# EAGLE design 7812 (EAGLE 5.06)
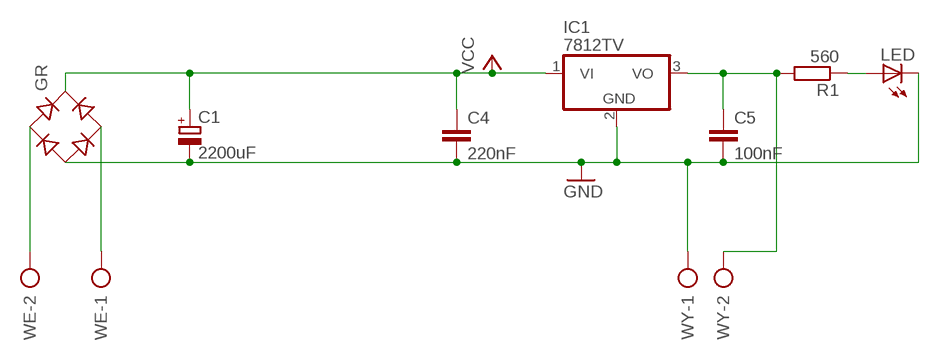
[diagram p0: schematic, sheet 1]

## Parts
C1  2200uF  CPOL-EUE7.5-16  [E7,5-16]
C4  220nF  C-EU025-030X050  [C025-030X050]
C5  100nF  C-EU025-030X050  [C025-030X050]
GR  RB1A  [RB1A]
IC1  7812TV  [TO220V]
LED  LED3MM  [LED3MM]
R1  560  R-EU_0207/10  [0207/10]
WE  AK300/2  [AK300/2]
WY  AK300/2  [AK300/2]

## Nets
GND: C1.- C4.2 C5.2 GR.- IC1.2(GND) LED.K(C) WY.1
N$1: GR.AC1 WE.2
N$2: GR.AC2 WE.1
N$4: C5.1 IC1.3(VO) R1.2 WY.2
N$5: LED.A R1.1
VCC: C1.+ C4.1 GR.+ IC1.1(VI)

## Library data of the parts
C1 = resistor:CPOL-EU: POLARIZED CAPACITOR, European symbol
C4 C5 = rcl:C-EU: CAPACITOR, European symbol
GR = rectifier:RB1A: RECTIFIER 1 A
IC1 = linear:78*: Positive VOLTAGE REGULATOR Source: http://cache.national.com/ds/LM/LM78L05.pdf http://www.fairchildsemi.com/ds/LM/LM7805.pdf
LED = led:LED: LED
R1 = rcl:R-EU_: RESISTOR, European symbol
WE WY = con-ptr500:AK300/2: CONNECTOR

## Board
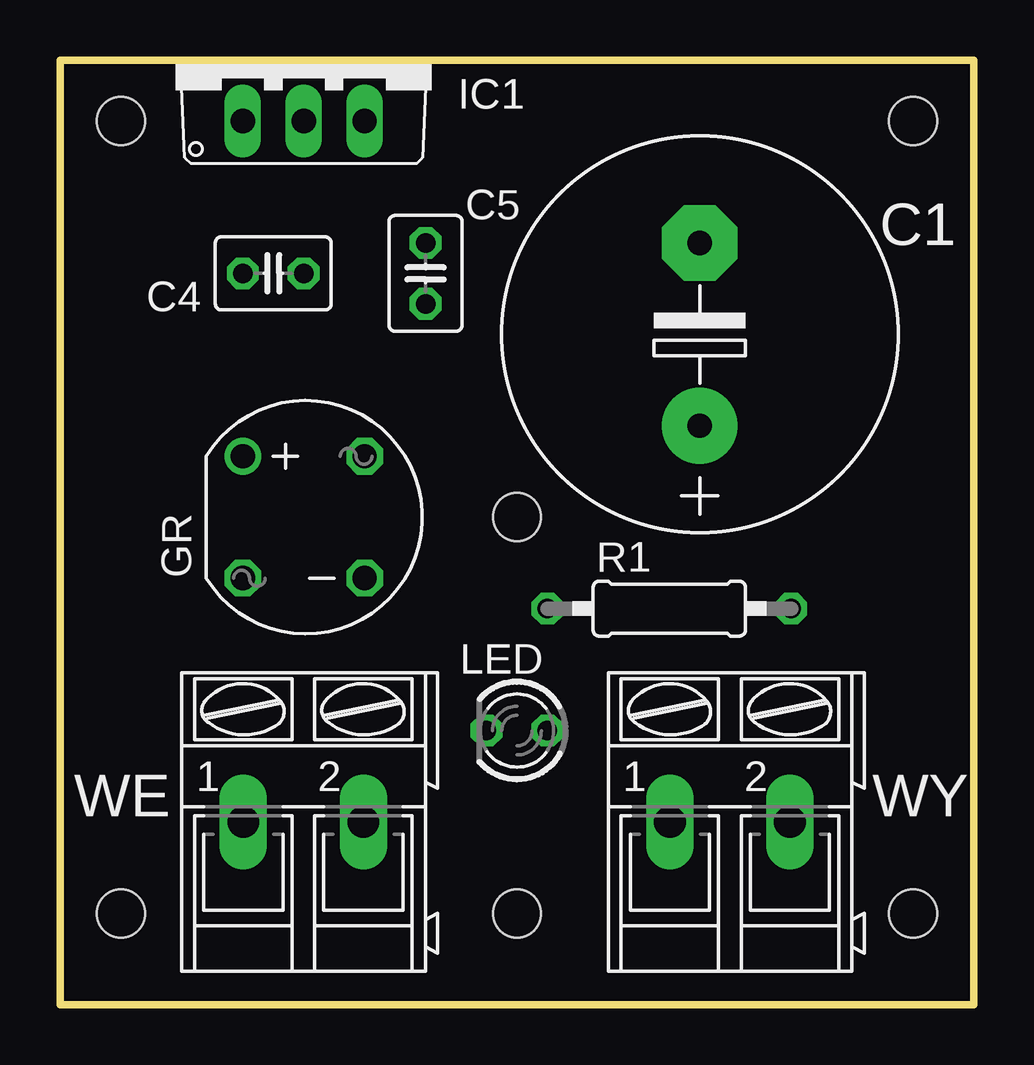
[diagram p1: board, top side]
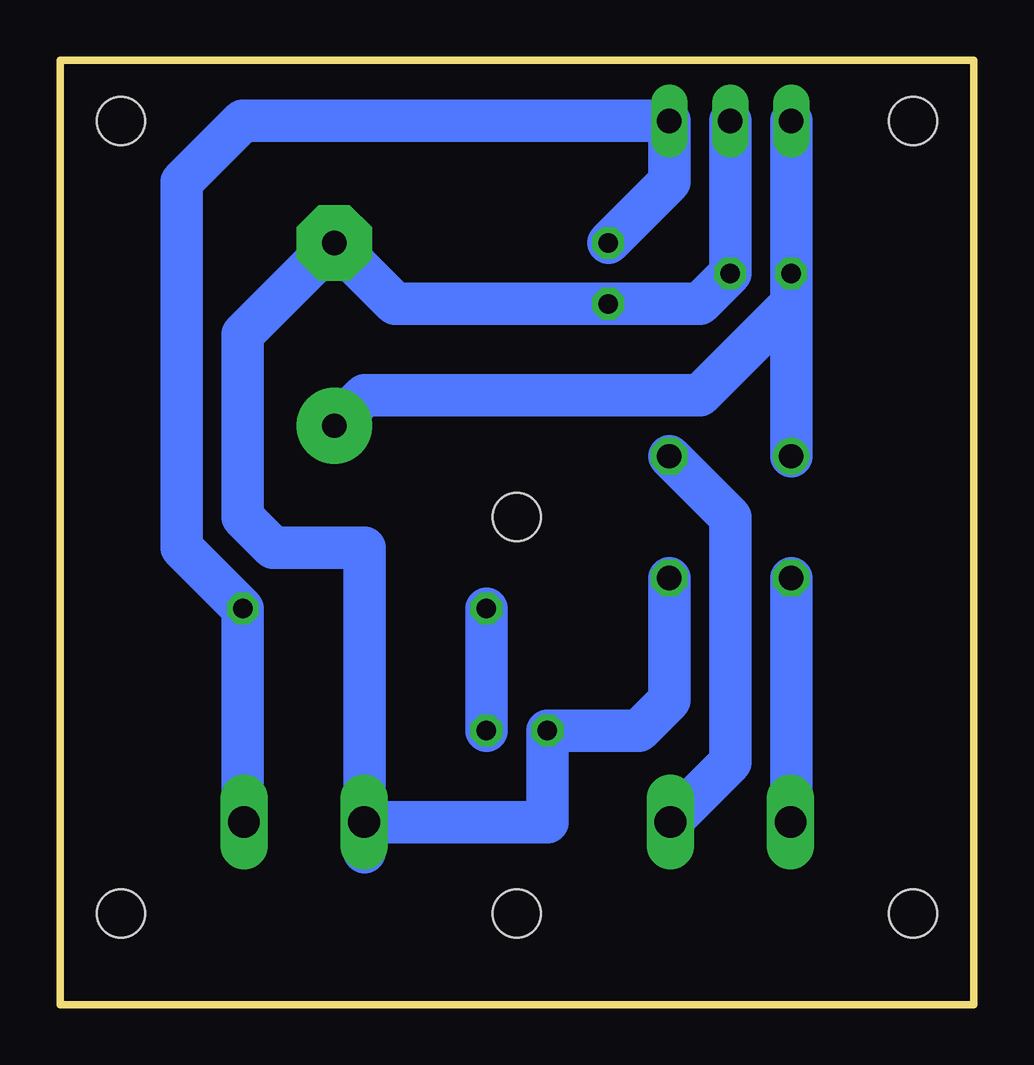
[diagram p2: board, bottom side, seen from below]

Size 38.1 x 39.37 mm. Coordinates in mm from the lower left corner, seen from the top.
Outline: 1.27,39.37 2.54,39.37
Outline: 2.54,39.37 38.1,39.37 38.1,0 0,0 0,39.37 2.54,39.37
Copper layers (1*16): Top 0.035mm / dielectric 1.5mm / Bottom 0.035mm
Design rules "default *": minimum track width 10mil, minimum drill 24mil, track to track 8mil, track to pad 8mil, pad to pad 8mil, via to via 8mil, smd to smd 8mil, copper to edge 40mil, drill to drill 8mil, minimum pad ring 10mil, minimum via ring 8mil, stop-mask expansion 4mil, vias tented up to drill 0mil, thermal gap 10mil
Holes 2 mm at 19.05,3.81 35.56,3.81 2.54,3.81 35.56,36.83 2.54,36.83 19.05,20.32

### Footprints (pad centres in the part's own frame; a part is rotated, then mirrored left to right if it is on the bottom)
E7,5-16 = drill 1.016 pad 3.15 round: + -3.81,0 | drill 1.016 pad 3.15 octagon: - 3.81,0
C025-030X050 = drill 0.813 octagon: 1 -1.27,0; 2 1.27,0
RB1A = drill 1.016 round: + -2.54,2.54 | drill 1.016 octagon: - 2.54,-2.54; AC1 2.54,2.54; AC2 -2.54,-2.54
TO220V = drill 1.016 long: 1 -2.54,-2.54; 2 0,-2.54; 3 2.54,-2.54
LED3MM = drill 0.813 octagon: A -1.27,0; K 1.27,0
0207/10 = drill 0.813 octagon: 1 -5.08,0; 2 5.08,0
AK300/2 = drill 1.321 long: 1 -2.515,0; 2 2.489,0

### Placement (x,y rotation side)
C1  26.67,27.94 90 top
C4  8.89,30.48 0 top
C5  15.24,30.48 270 top
GR  10.16,20.32 0 top
IC1  10.16,39.37 0 top
LED  19.05,11.43 180 top
R1  25.4,16.51 0 top
WE  10.16,7.62 0 top
WY  27.94,7.62 0 top

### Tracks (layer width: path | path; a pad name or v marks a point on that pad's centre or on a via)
GND
  Bottom 1.778: GR.- 12.7,12.7 13.97,11.43 LED.K 17.78,7.62 WY.1 25.43,6.38 25.4,6.35 25.4,19.05 29.21,19.05 30.48,20.32 30.48,27.94 C1.- 24.13,29.21 C5.2 11.43,29.21 C4.2 IC1.2
N$1
  Bottom 1.778: WE.2 10.16,10.11 10.16,20.32 GR.AC1
N$2
  Bottom 1.778: WE.1 7.62,7.64 GR.AC2
N$4
  Bottom 1.778: WY.2 30.48,7.67 R1.2 33.02,19.05 33.02,34.29 30.48,36.83 IC1.3 12.7,34.29 C5.1
N$5
  Bottom 1.778: LED.A R1.1
VCC
  Bottom 1.778: GR.+ 7.62,29.21 | 7.62,29.21 C4.1 IC1.1 | C1.+ 25.4,25.4 11.43,25.4 7.62,29.21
